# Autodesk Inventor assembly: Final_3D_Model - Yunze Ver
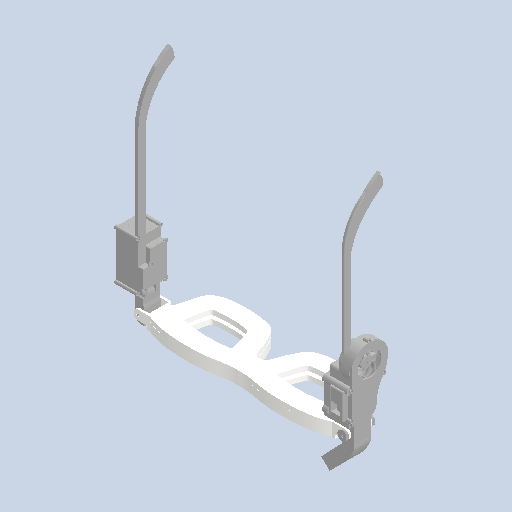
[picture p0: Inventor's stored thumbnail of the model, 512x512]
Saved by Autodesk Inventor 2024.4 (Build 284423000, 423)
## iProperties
Created: 2025-05
Part Number: Final_3D_Model - Yunze Ver
Document SubType Name: Assembly
Designer: AdminForWorker
Title: Final_3D_Model - Yunze Ver v10
Author: AdminForWorker
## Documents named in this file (5)
- c:\worker\convert-fusion-r02-cosv3\tmp\job-1\2\temp\files\be827049-a7f2-47ea-a815-8d9efd6bfce9\76a51928-4f62-4e3b-9115-739d9345d60f.iam
- c:\worker\convert-fusion-r02-cosv3\tmp\job-1\2\temp\files\be827049-a7f2-47ea-a815-8d9efd6bfce9\Glasses Leg (Left) v61.iam
- c:\worker\convert-fusion-r02-cosv3\tmp\job-1\2\temp\files\be827049-a7f2-47ea-a815-8d9efd6bfce9\Electrolux_blade v4.ipt
- c:\worker\convert-fusion-r02-cosv3\tmp\job-1\2\temp\files\be827049-a7f2-47ea-a815-8d9efd6bfce9\Glasses_init v17.iam
- c:\worker\convert-fusion-r02-cosv3\tmp\job-1\2\temp\files\be827049-a7f2-47ea-a815-8d9efd6bfce9\Glasses Leg (Right) v38.iam
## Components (4 placed, 4 different names)
1. Glasses Leg (Left) v61:1 [sub-assembly]
2. Electrolux_blade v4:2
3. Glasses_init v17:2 [sub-assembly]
4. Glasses Leg (Right) v38:1 [sub-assembly]
